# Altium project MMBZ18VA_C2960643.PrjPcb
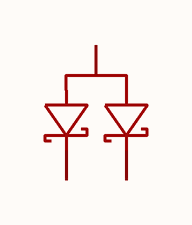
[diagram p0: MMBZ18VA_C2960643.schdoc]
1 sheet, 1 parts. Net scope: global (net labels, ports and power ports of the same name join across sheets).

## Sheet MMBZ18VA_C2960643.schdoc
size 127 x 101 mm

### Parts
U?  mmbz18va_c2960643  [SOT-23-3_L2.9-W1.3-P1.90-LS2.4-BR]  (value not drawn)

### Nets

Not connected (* = marked no-connect by the designer): U? 1 2 3

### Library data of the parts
U? = mmbz18va_c2960643: 极性:单向;反向截止电压(Vrwm):14.5V;钳位电压:25V;峰值脉冲电流(Ipp):1.6A;峰值脉冲功率(Ppp):40W;击穿电压(VBR):17.1V;; Manufacturer: JSMSEMI(杰盛微); AddInBom: yes; ModelId: c62791f0466c4ae2a892c056b845b0ca; ModelName: SOT-23-3P_L2.9-W1.3-H1.0-LS2.4-P0.95; ModelTransform: 98.425,114.173,0,180,0,0,0.0005,-0.0005,0; Polarity: 单向; Reverse Stand-Off Voltage (Vrwm): 14.5V; Clamping Voltage: 25V; Peak Pulse Current (Ipp): 1.6A; Peak Pulse Power Dissipation (Ppp): 40W; Voltage - Breakdown: 17.1V; Reverse Leakage Current (Ir): 50uA; Number of Channels: 双路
